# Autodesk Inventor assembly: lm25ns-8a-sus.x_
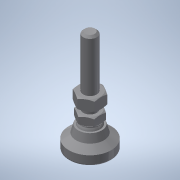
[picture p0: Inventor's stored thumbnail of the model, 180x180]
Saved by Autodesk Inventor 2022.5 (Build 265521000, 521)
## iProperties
Part Number: lm25ns-8a-sus.x_
Material: 一般
Document SubType Name: Assembly
Designer: ImaoCorp
Sending System: SOLIDWORKS 2017-2017317
MC: AMD64
MC_MODEL: Intel64 Family 6 Model 60 Stepping 3, GenuineIntel
OS: Windows_NT
FRU: Parasolid Version 29.0, build 201,  4-17-2017
FORMAT: text
GUISE: transmit
KEY: lm25ns-8a-sus
FILE: lm25ns-8a-sus.x_t
DATE: Mon Jul 01 17:50:40 2019
Author: ImaoCorp
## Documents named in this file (3)
- X:\14_SW2022-Inv2022\00_全2023-1023新製品(TCC)まで\l\lm25ns-8a-sus\LM25NS-8A-SUS.iam
- X:\14_SW2022-Inv2022\00_全2023-1023新製品(TCC)まで\l\lm25ns-8a-sus\lm25ns-8a-sus_01.ipt
- X:\14_SW2022-Inv2022\00_全2023-1023新製品(TCC)まで\l\lm25ns-8a-sus\lm25ns-8a-sus_02.ipt
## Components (2 placed, 2 different names)
1. lm25ns-8a-sus_01
2. lm25ns-8a-sus_02
